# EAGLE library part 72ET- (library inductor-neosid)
FILTER dual helix bandpass filter with tab, type E
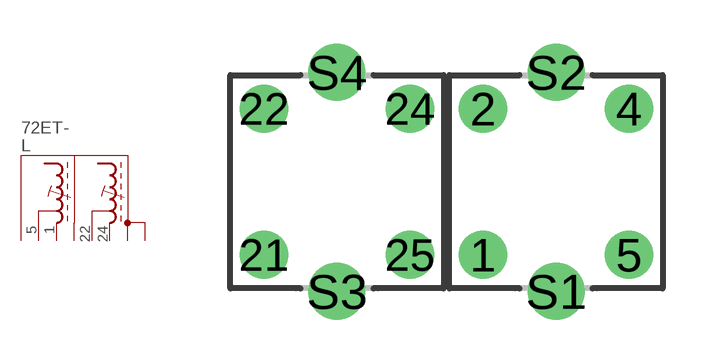
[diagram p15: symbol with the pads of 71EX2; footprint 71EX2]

Designator prefix L

## 72ET-512224 (OC_FARNELL: unknown; OC_NEWARK: unknown)  [71EX2]
1  GND1  pas
5  IN  pas
22  OUT  pas
24  GND2  pas
S1  S1  pas
S2  S2  pas
S3  S3  pas
S4  S4  pas

## 72ET-522225 (OC_FARNELL: unknown; OC_NEWARK: unknown)  [71EX2]
2  GND1  pas
5  IN  pas
22  OUT  pas
25  GND2  pas
S1  S1  pas
S2  S2  pas
S3  S3  pas
S4  S4  pas

## 72ET-422122 (OC_FARNELL: unknown; OC_NEWARK: unknown)  [71EX2]
2  GND1  pas
4  IN  pas
21  OUT  pas
22  GND2  pas
S1  S1  pas
S2  S2  pas
S3  S3  pas
S4  S4  pas

## 72ET-452122 (OC_FARNELL: unknown; OC_NEWARK: unknown)  [71EX2]
4  IN  pas
5  GND1  pas
21  OUT  pas
22  GND2  pas
S1  S1  pas
S2  S2  pas
S3  S3  pas
S4  S4  pas

## 72ET-542122 (OC_FARNELL: unknown; OC_NEWARK: unknown)  [71EX2]
4  GND1  pas
5  IN  pas
21  OUT  pas
22  GND2  pas
S1  S1  pas
S2  S2  pas
S3  S3  pas
S4  S4  pas

## 72ET-512122 (OC_FARNELL: unknown; OC_NEWARK: unknown)  [71EX2]
1  GND1  pas
5  IN  pas
21  OUT  pas
22  GND2  pas
S1  S1  pas
S2  S2  pas
S3  S3  pas
S4  S4  pas

## Footprint 71EX2 (pad centres in mm)
DUAL RF COIL ASSEMBLY 1 winding, 4 pads, grid 2.5 mm
drill 1.1 round: 1 1.25,-2.5; 2 1.25,2.5; 4 6.25,2.5; 5 6.25,-2.5; 21 -6.25,-2.5; 22 -6.25,2.5; 24 -1.25,2.5; 25 -1.25,-2.5
drill 1.3 round: S1 3.75,-3.75; S2 3.75,3.75; S3 -3.75,-3.75; S4 -3.75,3.75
